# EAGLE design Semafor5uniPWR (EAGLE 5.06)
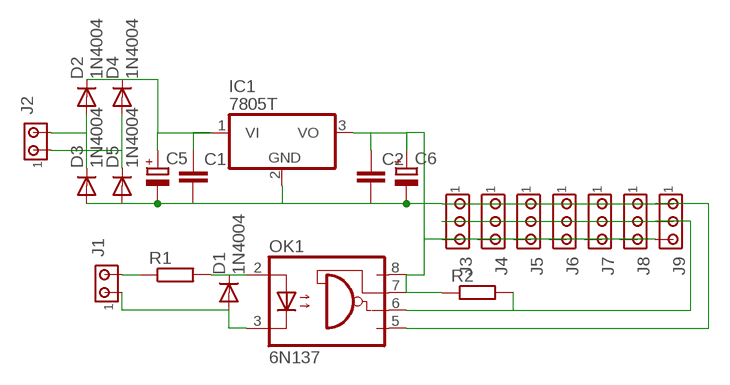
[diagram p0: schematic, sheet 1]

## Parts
C1  C-EU025-025X050  [C025-025X050]
C2  C-EU025-025X050  [C025-025X050]
C5  CPOL-EUE2.5-7  [E2,5-7]
C6  CPOL-EUE2.5-7  [E2,5-7]
D1  1N4004  [DO41-10]
D2  1N4004  [DO41-10]
D3  1N4004  [DO41-10]
D4  1N4004  [DO41-10]
D5  1N4004  [DO41-10]
IC1  7805T  [TO220H]
J1  MTA02-100  [10X02MTA]
J2  MTA02-100  [10X02MTA]
J3  MTA03-100  [10X03MTA]
J4  MTA03-100  [10X03MTA]
J5  MTA03-100  [10X03MTA]
J6  MTA03-100  [10X03MTA]
J7  MTA03-100  [10X03MTA]
J8  MTA03-100  [10X03MTA]
J9  MTA03-100  [10X03MTA]
OK1  6N137  [DIL08]
R1  R-EU_0207/10  [0207/10]
R2  R-EU_0207/10  [0207/10]

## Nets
N$1: C1.2 C2.2 C5.- C6.- D3.A D5.A IC1.2(GND) J3.1 J4.1 J5.1 J6.1 J7.1 J8.1 J9.1 OK1.5(GND)
N$2: C2.1 C6.+ IC1.3(VO) J3.3 J4.3 J5.3 J6.3 J7.3 J8.3 J9.3 OK1.7(VE) OK1.8(VCC) R2.1
N$3: C1.1 C5.+ D2.C D4.C IC1.1(VI)
N$4: D4.A D5.C J2.1
N$5: D2.A D3.C J2.2
N$6: J1.2 R1.1
N$7: D1.C OK1.2(A) R1.2
N$8: D1.A J1.1 OK1.3(C)
N$11: J3.2 J4.2 J5.2 J6.2 J7.2 J8.2 J9.2 OK1.6(VO) R2.2

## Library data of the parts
C1 C2 = resistor:C-EU: CAPACITOR, European symbol
C5 C6 = resistor:CPOL-EU: POLARIZED CAPACITOR, European symbol
D1-D5 = diode:1N4004: DIODE
IC1 = linear:78*: Positive VOLTAGE REGULATOR Source: http://cache.national.com/ds/LM/LM78L05.pdf http://www.fairchildsemi.com/ds/LM/LM7805.pdf
J1 J2 = con-amp:MTA02-100: AMP connector
J3-J9 = con-amp:MTA03-100: AMP connector
OK1 = optocoupler:6N137: MOTOROLA OPTO COUPLER
R1 R2 = resistor:R-EU_: RESISTOR, European symbol

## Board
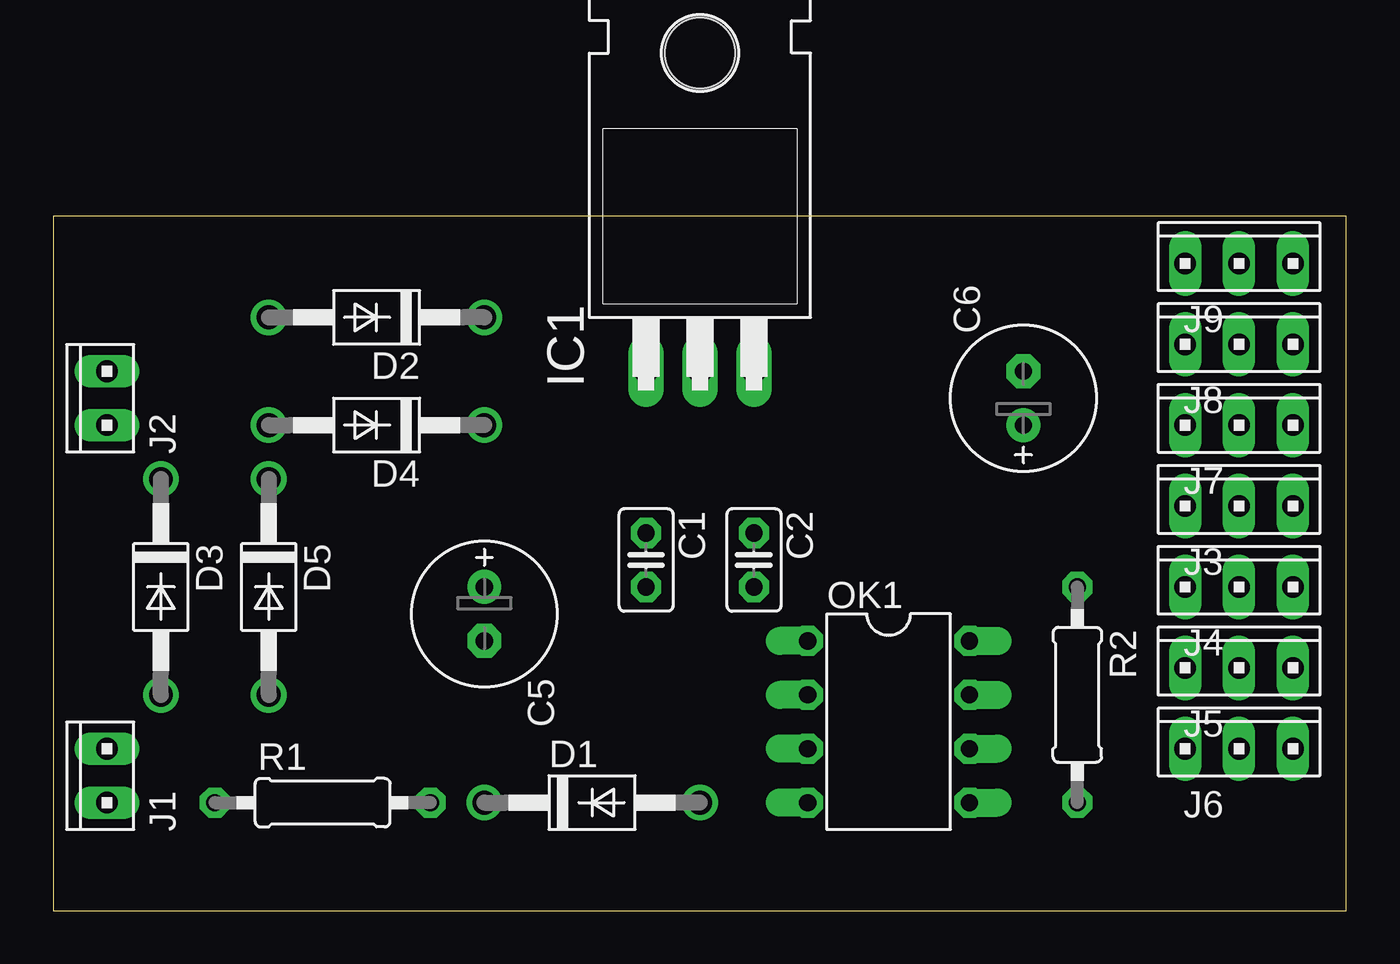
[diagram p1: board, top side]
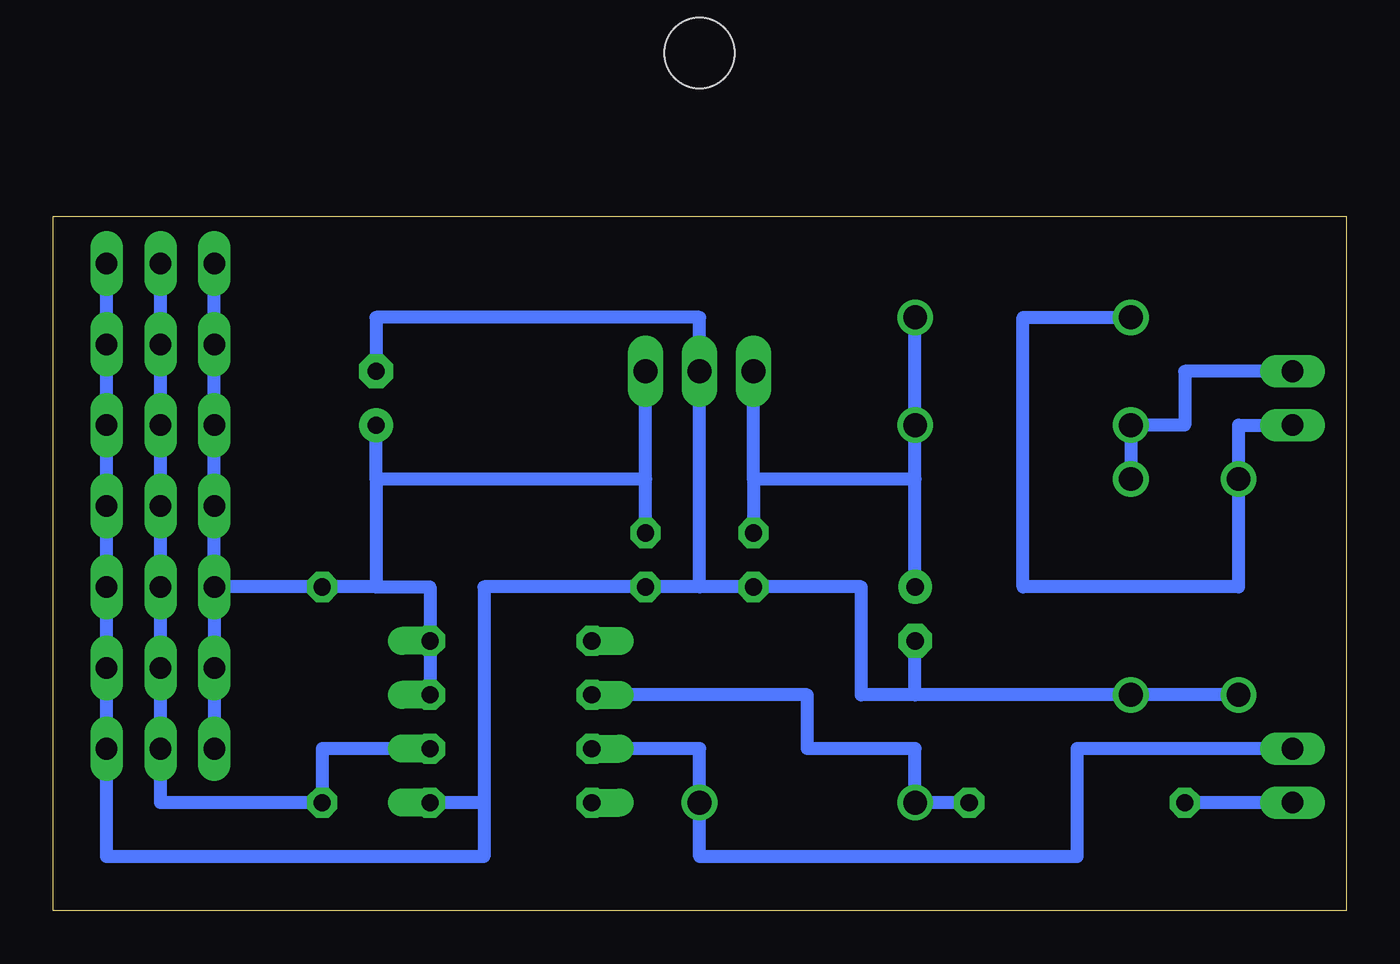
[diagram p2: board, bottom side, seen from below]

Size 60.94 x 32.69 mm. Coordinates in mm from the lower left corner, seen from the top.
Outline: 0,0 60.94,0 60.94,32.69 0,32.69 0,0
Copper layers (1*16): Top 0.035mm / dielectric 1.5mm / Bottom 0.035mm
Design rules "default": minimum track width 10mil, minimum drill 24mil, track to track 8mil, track to pad 8mil, pad to pad 8mil, via to via 8mil, smd to smd 8mil, copper to edge 40mil, drill to drill 8mil, minimum pad ring 10mil, minimum via ring 8mil, stop-mask expansion 4mil, vias tented up to drill 0mil, thermal gap 10mil

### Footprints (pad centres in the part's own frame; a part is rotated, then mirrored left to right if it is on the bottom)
C025-025X050 = drill 0.813 octagon: 1 -1.27,0; 2 1.27,0
E2,5-7 = drill 0.813 pad 1.6 round: + -1.27,0 | drill 0.813 pad 1.6 octagon: - 1.27,0
DO41-10 = drill 1.118 round: A 5.08,0; C -5.08,0
TO220H = drill 1.118 long: 1 -2.54,-10.16; 2 0,-10.16; 3 2.54,-10.16 | hole 3.302: 0,4.826
10X02MTA = drill 1.016 long: 1 1.27,0; 2 -1.27,0
10X03MTA = drill 1.016 long: 1 2.54,0; 2 0,0; 3 -2.54,0
DIL08 = drill 0.813 offset: 1 -3.81,-3.81; 2 -1.27,-3.81; 3 1.27,-3.81; 4 3.81,-3.81; 5 3.81,3.81; 6 1.27,3.81; 7 -1.27,3.81; 8 -3.81,3.81
0207/10 = drill 0.813 octagon: 1 -5.08,0; 2 5.08,0

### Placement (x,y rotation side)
C1  27.94,16.51 270 top
C2  33.02,16.51 270 top
C5  20.32,13.97 270 top
C6  45.72,24.13 90 top
D1  25.4,5.08 0 top
D2  15.24,27.94 180 top
D3  5.08,15.24 270 top
D4  15.24,22.86 180 top
D5  10.16,15.24 270 top
IC1  30.48,35.56 0 top
J1  2.54,6.35 90 top
J2  2.54,24.13 90 top
J3  55.88,19.05 0 top
J4  55.88,15.24 0 top
J5  55.88,11.43 0 top
J6  55.88,7.62 0 top
J7  55.88,22.86 0 top
J8  55.88,26.67 0 top
J9  55.88,30.48 0 top
OK1  39.37,8.89 270 top
R1  12.7,5.08 0 top
R2  48.26,10.16 270 top

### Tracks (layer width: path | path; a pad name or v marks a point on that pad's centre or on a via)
N$1
  Bottom 0.254: 30.48,15.24 C2.2
  Bottom 0.61: D3.A D5.A 20.32,10.16 | 30.48,15.24 IC1.2 30.48,27.94 45.72,27.94 C6.- | J9.1 J8.1 J7.1 J3.1 J4.1 J5.1 J6.1 58.42,2.54 40.64,2.54 40.64,5.08 | 30.48,15.24 C1.2 22.86,15.24 22.86,10.16 20.32,10.16 | 30.48,15.24 40.64,15.24 40.64,5.08 | 40.64,5.08 OK1.5 | 20.32,10.16 C5.-
N$2
  Bottom 0.61: J9.3 J8.3 J7.3 J3.3 J4.3 | J6.3 J5.3 J4.3 | C2.1 33.02,20.32 | 33.02,20.32 IC1.3 | OK1.7 OK1.8 43.18,15.24 45.72,15.24 | 45.72,15.24 R2.1 J4.3 | 45.72,20.32 45.72,15.24 | 33.02,20.32 45.72,20.32 | 45.72,20.32 C6.+
N$3
  Bottom 0.61: D2.C D4.C 20.32,20.32 | 20.32,20.32 27.94,20.32 | 27.94,20.32 C1.1 | 27.94,20.32 IC1.1 | C5.+ 20.32,20.32
N$4
  Bottom 0.61: J2.1 7.62,25.4 7.62,22.86 D4.A D5.C
N$5
  Bottom 0.61: J2.2 5.08,22.86 D3.C 5.08,15.24 15.24,15.24 15.24,27.94 D2.A
N$6
  Bottom 0.61: J1.2 R1.1 J1.2
N$7
  Bottom 0.61: R1.2 D1.C 20.32,7.62 25.4,7.62 25.4,10.16 OK1.2
N$8
  Bottom 0.61: OK1.3 30.48,7.62 D1.A 30.48,2.54 12.7,2.54 12.7,7.62 J1.1
N$9  (via drill 0.5 pad 1.42)
  other vias: 53.34,30.48 10.16,27.94 20.32,27.94 10.16,22.86 10.16,20.32 5.08,20.32 20.32,22.86 10.16,10.16 5.08,10.16 7.62,5.08 2.54,5.08 2.54,7.62 2.54,25.4 2.54,22.86 17.78,5.08 20.32,5.08 20.32,12.7 20.32,15.24 27.94,25.4 30.48,25.4 33.02,25.4 27.94,17.78 27.94,15.24 33.02,17.78 33.02,15.24 45.72,25.4 45.72,22.86 30.48,5.08 35.56,12.7 35.56,10.16 35.56,7.62 35.56,5.08 43.18,12.7 43.18,10.16 43.18,7.62 43.18,5.08 48.26,15.24 48.26,5.08 53.34,30.48 55.88,30.48 58.42,30.48 53.34,22.86 55.88,22.86 58.42,22.86 53.34,15.24 55.88,15.24 58.42,15.24 53.34,7.62 55.88,7.62 58.42,7.62 53.34,26.67 55.88,26.67 58.42,26.67 53.34,19.05 55.88,19.05 58.42,19.05 53.34,11.43 55.88,11.43 58.42,11.43
N$11
  Bottom 0.61: OK1.6 48.26,7.62 R2.2 55.88,5.08 J6.2 J5.2 J4.2 J3.2 J7.2 J8.2 J9.2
